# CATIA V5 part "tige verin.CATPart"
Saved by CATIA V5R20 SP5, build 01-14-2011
Part number: tige verin
Bounding box of the stored display mesh (mm): x -528.824 to 3649.198, y -800 to 471.869, z 7931.945 to 9758.98
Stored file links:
  M:\EU_thinkMotion\IAO_2010\iao\IAO_MMS_Groupe1\Problemes\gduval\Gduval\train d'aterrissage squelette + piece kinematic\tige verin.CATPart
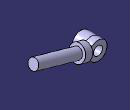
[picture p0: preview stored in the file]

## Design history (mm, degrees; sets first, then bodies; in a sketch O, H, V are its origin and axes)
Body1 (main body)
  Point1: stored without definition
  Point2: stored without definition
  Sketch1 on zx-plane, origin (0, 0, 0), H (-1, 0, 0), V (0, 0, 1)
    point P1 (0, 8460.769)
    reference projected point E1 (0, 8460.769) from Point1
    axis line L1 (0, 8460.769) -> (-9523.6856, 11155.8159)
    reference projected point E2 (-9261.784, 11081.702) from Point2
    line L2 (-475.3674, 9085.8251) -> (-889.1199, 9202.9102)
    line L3 (-475.3674, 9085.8251) -> (-603.8888, 8631.6596)
    point P5 (-603.8888, 8631.6596)
    line L4 (-889.1199, 9202.9102) -> (-935.9539, 9037.4093)
    line L5 (-935.9539, 9037.4093) -> (-3485.8235, 9758.9805)
    line L6 (-3485.8235, 9758.9805) -> (-3567.5108, 9470.3161)
    point P8 (-3567.5108, 9470.3161)
    reference projected point E3 (0, 8460.769) from Point1
    distance L5 L1 = 300
    distance L6 L3 = 3080
    distance L4 L6 = 2650
    distance L2 L1 = 472
    distance E3 L4 = 1057.6028
    coincidence: P1 E1, L1 E2, P5 L1, P8 L1
    perpendicularity: L3 L1
    parallelism: L4 L3, L5 L2
  Shaft1: profile Sketch1, axis Sketch1.L1, angle 360
  Sketch2 on zx-plane, origin (0, 0, 0), H (-1, 0, 0), V (0, 0, 1)
    arc A1 centre (0, 8460.769) radius 528.8238 from (508.8421, 8316.775) to (-343.6738, 8862.693) ccw
    point P1 (0, 8460.769)
    point P2 (508.8421, 8316.775)
    point P3 (-343.6738, 8862.693)
    reference projected point E1 (0, 8460.769) from Point1
    axis line L1 (1099.104, 8149.7406) -> (-10371.5945, 11395.7602)
    reference projected point E2 (-9261.784, 11081.702) from Point2
    reference projected point E3 (0, 8460.769) from Point1
    line L2 (-343.6738, 8862.693) -> (-498.7746, 9003.1096)
    point P6 (-498.7746, 9003.1096)
    reference intersected line E4 (-475.3674, 9085.8251) -> (-732.4102, 8177.4942) from face of Shaft1 from Sketch1.L3
    line L3 (-498.7746, 9003.1096) -> (-603.8888, 8631.6596)
    point P7 (-603.8888, 8631.6596)
    point P8 (-503.3224, 8298.531)
    point P9 (508.8421, 8316.775)
    arc A2 centre (0, 8460.769) radius 528.8238 from (508.8421, 8316.775) to (-503.3224, 8298.531) cw
    point P11 (-709.0031, 8260.2097)
    line L4 (-503.3224, 8298.531) -> (-709.0031, 8260.2097)
    point P12 (-603.8888, 8631.6596)
    line L5 (-709.0031, 8260.2097) -> (-603.8888, 8631.6596)
    radius A1 = 528.8238
    coincidence: P1 E1, E2 L1, L1 E3, P2 L1, P6 E4, P7 L1, P2 P9, P7 P12
    perpendicularity: L3 L1
    symmetry: P3 P8 L1, P2 P9 L1, A1 A2 L1, P6 P11 L1, L2 L4 L1, P7 P12 L1, L3 L5 L1
  Pad1: profile Sketch2, direction (0, 1, 0), length 200, mirrored extent
  Sketch3 on start face of Pad1, origin (-126.8662, -200, 8407.6865), H (1, 0, 0), V (0, 0, 1)
    point P1 (126.8662, 53.0825)
    reference projected point E1 (126.8662, 53.0825) from Point1
    coincidence: P1 E1
  Hole1: placed by Sketch3, at (0, -200, 8460.769) direction (0, 1, 0), diameter 520, through (limit type 6)
  Sketch4 on start face of Pad1, origin (0, -200, 0), H (1, 0, 0), V (0, 0, 1)
    circle A1 centre (0, 8460.769) radius 260
    reference projected circle E1 centre (0, 8460.769) radius 260 from edge [face of Hole1 | start face of Pad1]
    circle A2 centre (0, 8460.769) radius 528.8238
    reference projected arc E2 centre (0, 8460.769) radius 528.8238 from (343.6738, 8862.693) to (-508.8421, 8316.775) ccw from edge [start face of Pad1 | face of Pad1 from Sketch2.A1]
    coincidence: A1 E1, A2 E2
  Pad2: profile Sketch4, direction (0, -1, 0), length 600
